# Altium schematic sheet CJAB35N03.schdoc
size 127 x 101 mm
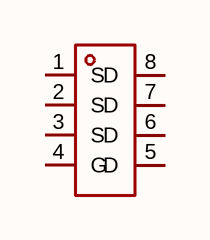
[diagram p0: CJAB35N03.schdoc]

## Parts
Q?  cjab35n03  [POWERPAK-1212-8_L3.0-W3.0-P0.65-LS3.3-BL]  (value not drawn)

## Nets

Not connected (* = marked no-connect by the designer): Q? 1(S) 2(S) 3(S) 4(G) 5(D) 6(D) 7(D) 8(D)

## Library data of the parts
Q? = cjab35n03: 数量:1个N沟道;漏源电压(Vdss):30V;连续漏极电流(Id):35A;导通电阻(RDS(on)):7mΩ@10V;耗散功率(Pd):45W;阈值电压(Vgs(th)):1V;; Manufacturer: CJ(江苏长电/长晶); AddInBom: yes; ModelId: 74fc8db97a8d4d328d7f3b4acba39a5e; ModelTransform: 129.921,129.921,0,0,0,0,0,0,0; Number: 1个N沟道; Drain to Source Voltage: 30V; Current - Continuous Drain(Id): 35A; Pd - Power Dissipation: 45W; Gate Threshold Voltage (Vgs(th)): 1V; Gate Charge(Qg): 40nC@10V; Input Capacitance(Ciss): 2.013nF; Reverse Transfer Capacitance (Crss@Vds): 228pF; Type: N沟道; Output Capacitance(Coss): 257pF; Vgs: ±20V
